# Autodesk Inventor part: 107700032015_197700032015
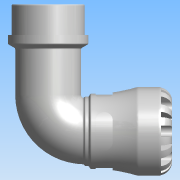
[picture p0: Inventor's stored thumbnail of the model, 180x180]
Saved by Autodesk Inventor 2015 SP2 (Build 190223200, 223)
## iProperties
Created: 2016-12
Part Number: 107700032015_197700032015
Material: PVC-Piping
Description: PLASSON 90° ELBOW WITH MALE INTEGRAL BRASS 32X1.1/2" SERIES 1
Document SubType Name: Modeling
Designer: KIM
Mass: 664.223 g
Surface Area: 733.008 cm^2
Volume: 474.445 cm^3
Density: 1.4 g/cm^3
Appearance: Smooth - White
Author: KIM
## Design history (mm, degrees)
derived "1077.ipt"
feature "Solid1::1077.ipt"
tag "TaggingFeature1"
body "Solid1"
other parameters: "d1" = 22.68, "d2" = 32, "d4" = 58, "d8" = 49.3, "d13" = 7.2, "d14" = 7.2, "d15" = 0, "d17" = 360 deg, "d19" = 8 deg, "d20" = 0.64, "d21" = 0.64, "d22" = 8 deg, "d24" = 0, "d26" = 360 deg, "d33" = 5.8, "d43" = 45.24, "d51" = 0.58, "d54" = 11.2, "d55" = 7.04, "d57" = 14.112, "d58" = 0, "d74" = 0, "d78" = 54, "d82" = 0.64, "d115" = 360 deg, "d207" = 90 deg, "d228" = 9.52, "d247" = 1.16, "d248" = 3.24, "d268" = 27.115, "d269" = 3.24, "d270" = 81, "d276" = 47.803, "d278" = 52.5833, "d279" = 83, "d280" = 26, "d281" = 7.17045, "d283" = 43.0227, "d286" = 0, "d287" = 0, "d288" = 33.4621, "d290" = 1.10865, "d292" = 30 deg, "d294" = 4.7803, "d296" = 30 deg, "d_" = 32, "E_" = 58, "l_" = 54, "A_" = 81, "A_1" = 83, "R_" = 47.803, "d9" = 9, "d11" = 58, "d289" = 33.4621
